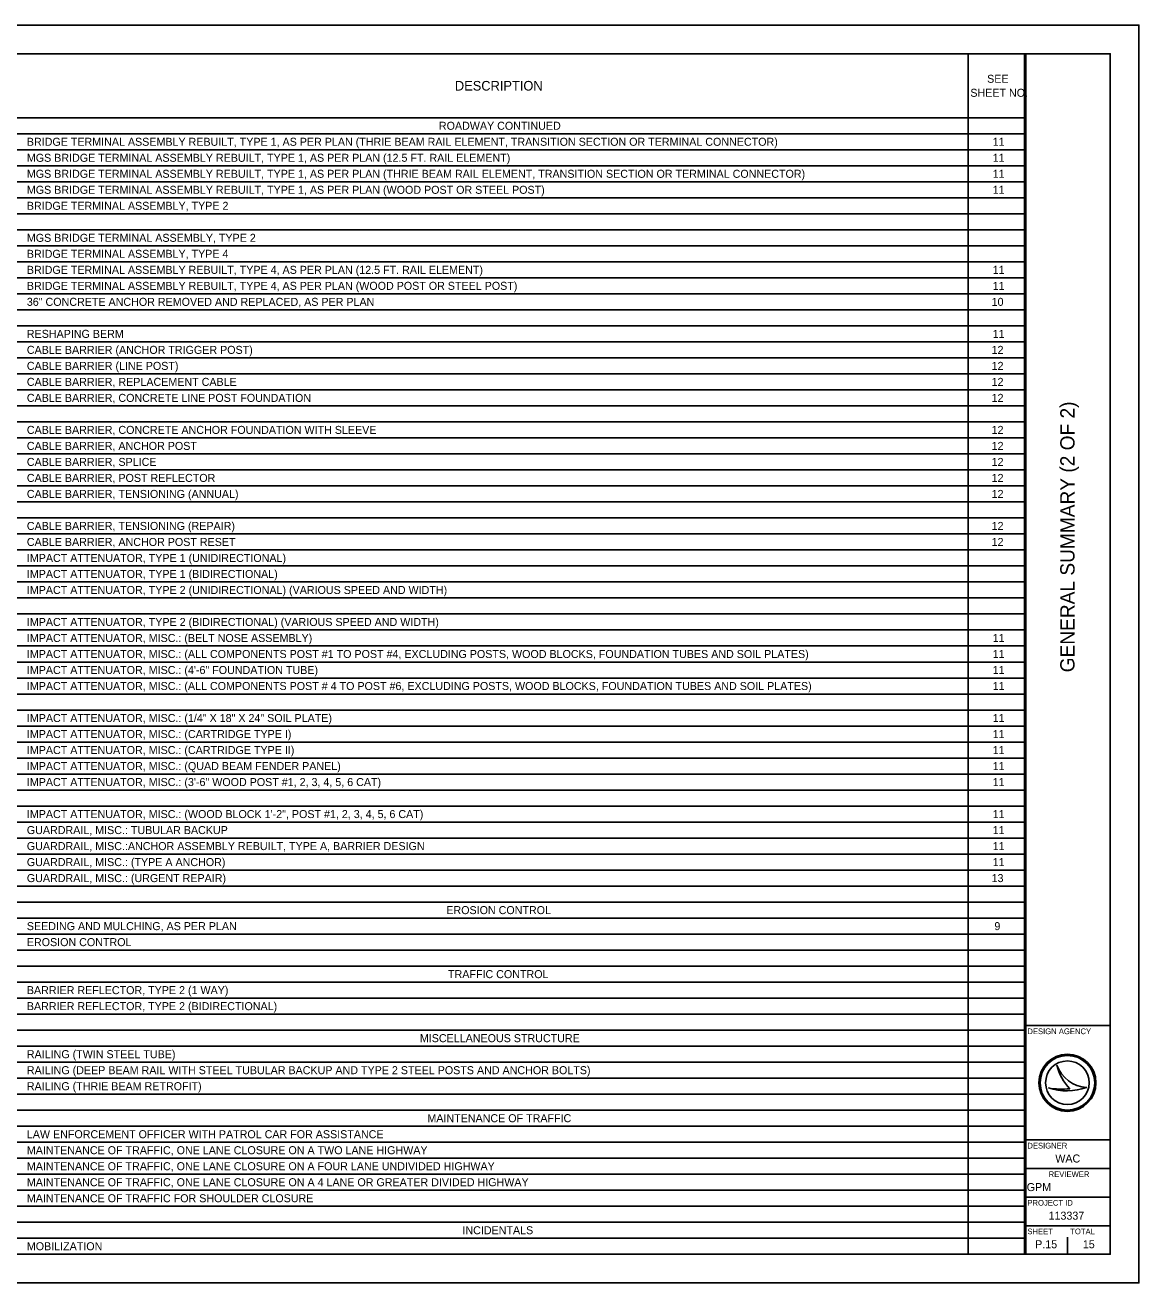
# Model space of a CAD drawing. Extents: x 0 to 34, y 0 to 22.
# Drawn here: x 14.52 to 34, y 0 to 22 of the extents above; entities that cross this region are included whole.
import ezdxf

# ---------------------------------------------------------------- set-up
doc = ezdxf.new("R2010")
doc.units = 0
for name, color, linetype in [('Default', 7, 'Continuous'), ('SH_Border', 7, 'Continuous'), ('SH_Cut_Line', 7, 'Continuous'), ('SH_Data', 7, 'Continuous')]:
    doc.layers.add(name, color=color, linetype=linetype)

msp = doc.modelspace()

# ---------------------------------------------------------------- linework, layer by layer
at = {"layer": 'Default'}
for p, q in [((1.5, 21.5), (32.02, 21.5)), ((31.015, 21.5), (31.015, 0.5)), ((32.02, 21.5), (32.02, 0.5)), ((1.5, 20.38), (32.02, 20.38)), ((1.5, 20.1), (32.02, 20.1)), ((1.5, 19.82), (32.02, 19.82)), ((1.5, 19.54), (32.02, 19.54)), ((1.5, 19.26), (32.02, 19.26)), ((1.5, 18.98), (32.02, 18.98)), ((1.5, 18.7), (32.02, 18.7)), ((1.5, 18.42), (32.02, 18.42)), ((1.5, 18.14), (32.02, 18.14)), ((1.5, 17.86), (32.02, 17.86)), ((1.5, 17.58), (32.02, 17.58)), ((1.5, 17.3), (32.02, 17.3)), ((1.5, 17.02), (32.02, 17.02)), ((1.5, 16.74), (32.02, 16.74)), ((1.5, 16.46), (32.02, 16.46)), ((1.5, 16.18), (32.02, 16.18)), ((1.5, 15.9), (32.02, 15.9)), ((1.5, 15.62), (32.02, 15.62)), ((1.5, 15.34), (32.02, 15.34)), ((1.5, 15.06), (32.02, 15.06)), ((1.5, 14.78), (32.02, 14.78)), ((1.5, 14.5), (32.02, 14.5)), ((1.5, 14.22), (32.02, 14.22)), ((1.5, 13.94), (32.02, 13.94)), ((1.5, 13.66), (32.02, 13.66)), ((1.5, 13.38), (32.02, 13.38)), ((1.5, 13.1), (32.02, 13.1)), ((1.5, 12.82), (32.02, 12.82)), ((1.5, 12.54), (32.02, 12.54)), ((1.5, 12.26), (32.02, 12.26)), ((1.5, 11.98), (32.02, 11.98)), ((1.5, 11.7), (32.02, 11.7)), ((1.5, 11.42), (32.02, 11.42)), ((1.5, 11.14), (32.02, 11.14)), ((1.5, 10.86), (32.02, 10.86)), ((1.5, 10.58), (32.02, 10.58)), ((1.5, 10.3), (32.02, 10.3)), ((1.5, 10.02), (32.02, 10.02)), ((1.5, 9.74), (32.02, 9.74)), ((1.5, 9.46), (32.02, 9.46)), ((1.5, 9.18), (32.02, 9.18)), ((1.5, 8.9), (32.02, 8.9)), ((1.5, 8.62), (32.02, 8.62)), ((1.5, 8.34), (32.02, 8.34)), ((1.5, 8.06), (32.02, 8.06)), ((1.5, 7.78), (32.02, 7.78)), ((1.5, 7.5), (32.02, 7.5)), ((1.5, 7.22), (32.02, 7.22)), ((1.5, 6.94), (32.02, 6.94)), ((1.5, 6.66), (32.02, 6.66)), ((1.5, 6.38), (32.02, 6.38)), ((1.5, 6.1), (32.02, 6.1)), ((1.5, 5.82), (32.02, 5.82)), ((1.5, 5.54), (32.02, 5.54)), ((1.5, 5.26), (32.02, 5.26)), ((1.5, 4.98), (32.02, 4.98)), ((1.5, 4.7), (32.02, 4.7)), ((1.5, 4.42), (32.02, 4.42)), ((1.5, 4.14), (32.02, 4.14)), ((1.5, 3.86), (32.02, 3.86)), ((1.5, 3.58), (32.02, 3.58)), ((1.5, 3.3), (32.02, 3.3)), ((1.5, 3.02), (32.02, 3.02)), ((1.5, 2.74), (32.02, 2.74)), ((1.5, 2.46), (32.02, 2.46)), ((1.5, 2.18), (32.02, 2.18)), ((1.5, 1.9), (32.02, 1.9)), ((1.5, 1.62), (32.02, 1.62)), ((1.5, 1.34), (32.02, 1.34)), ((1.5, 1.06), (32.02, 1.06)), ((1.5, 0.78), (32.02, 0.78)), ((1.5, 0.5), (32.02, 0.5))]:
    msp.add_line(p, q, dxfattribs=at)
at = {"layer": 'SH_Border'}
for p, q in [((32, 0.5), (32, 21.5)), ((32, 4.5), (33.5, 4.5)), ((32, 2.5), (33.5, 2.5)), ((32, 2), (33.5, 2)), ((32, 1.5), (33.5, 1.5)), ((32, 1), (33.5, 1))]:
    msp.add_line(p, q, dxfattribs=at)
msp.add_lwpolyline([(1.5, 21.5), (33.5, 21.5), (33.5, 0.5), (1.5, 0.5)], close=True, dxfattribs=at)
at = {"layer": 'SH_Cut_Line'}
msp.add_lwpolyline([(0, 0), (34, 0), (34, 22), (0, 22)], close=True, dxfattribs=at)
at = {"layer": 'SH_Data'}
for p, q in [((32.567, 3.81), (32.567, 3.81)), ((32.417, 3.41), (32.417, 3.41)), ((32.75, 3.5), (32.75, 3.5)), ((33.087, 3.419), (33.087, 3.419)), ((32.375, 0.675), (32.375, 0.675)), ((32.75, 0.5), (32.75, 0.8))]:
    msp.add_line(p, q, dxfattribs=at)
for radius in [0.5, 0.477, 0.477, 0.382]:
    msp.add_circle((32.75, 3.5), radius, dxfattribs=at)
for centre, radius, start, end in [((33.116, 3.998), 0.58, 198.9257, 198.9319), ((33.347, 3.97), 0.796, 191.6379, 191.6421), ((33.116, 3.998), 0.58, 198.9319, 267.1657), ((33.347, 3.97), 0.796, 191.6421, 226.0947), ((32.739, 4.37), 1.013, 251.4576, 290.0832), ((32.648, 4.654), 1.266, 259.4964, 259.4995), ((32.739, 4.37), 1.013, 251.4527, 251.4576), ((32.648, 4.654), 1.266, 259.4995, 276.6672)]:
    msp.add_arc(centre, radius, start, end, dxfattribs=at)

# ---------------------------------------------------------------- texts
at = {"layer": 'Default'}
for s, height, p in [('SEE ', 0.14, (31.346, 20.992)), ('DESCRIPTION', 0.168, (22.034, 20.856)), ('SHEET NO.', 0.14, (31.052, 20.747)), ('ROADWAY CONTINUED', 0.14, (21.754, 20.17)), ('BRIDGE TERMINAL ASSEMBLY REBUILT, TYPE 1, AS PER PLAN (THRIE BEAM RAIL ELEMENT, TRANSITION SECTION OR TERMINAL CONNECTOR)', 0.14, (14.545, 19.89)), ('11', 0.14, (31.443, 19.89)), ('MGS BRIDGE TERMINAL ASSEMBLY REBUILT, TYPE 1, AS PER PLAN (12.5 FT. RAIL ELEMENT)', 0.14, (14.545, 19.61)), ('11', 0.14, (31.443, 19.61)), ('MGS BRIDGE TERMINAL ASSEMBLY REBUILT, TYPE 1, AS PER PLAN (THRIE BEAM RAIL ELEMENT, TRANSITION SECTION OR TERMINAL CONNECTOR)', 0.14, (14.545, 19.33)), ('11', 0.14, (31.443, 19.33)), ('MGS BRIDGE TERMINAL ASSEMBLY REBUILT, TYPE 1, AS PER PLAN (WOOD POST OR STEEL POST)', 0.14, (14.545, 19.05)), ('11', 0.14, (31.443, 19.05)), ('BRIDGE TERMINAL ASSEMBLY, TYPE 2', 0.14, (14.545, 18.77)), ('MGS BRIDGE TERMINAL ASSEMBLY, TYPE 2', 0.14, (14.545, 18.21)), ('BRIDGE TERMINAL ASSEMBLY, TYPE 4', 0.14, (14.545, 17.93)), ('BRIDGE TERMINAL ASSEMBLY REBUILT, TYPE 4, AS PER PLAN (12.5 FT. RAIL ELEMENT)', 0.14, (14.545, 17.65)), ('11', 0.14, (31.443, 17.65)), ('BRIDGE TERMINAL ASSEMBLY REBUILT, TYPE 4, AS PER PLAN (WOOD POST OR STEEL POST)', 0.14, (14.545, 17.37)), ('11', 0.14, (31.443, 17.37)), ('36" CONCRETE ANCHOR REMOVED AND REPLACED, AS PER PLAN', 0.14, (14.545, 17.09)), ('10', 0.14, (31.424, 17.09)), ('RESHAPING BERM', 0.14, (14.545, 16.53)), ('11', 0.14, (31.443, 16.53)), ('CABLE BARRIER (ANCHOR TRIGGER POST)', 0.14, (14.545, 16.25)), ('12', 0.14, (31.424, 16.25)), ('CABLE BARRIER (LINE POST)', 0.14, (14.545, 15.97)), ('12', 0.14, (31.424, 15.97)), ('CABLE BARRIER, REPLACEMENT CABLE', 0.14, (14.545, 15.69)), ('12', 0.14, (31.424, 15.69)), ('CABLE BARRIER, CONCRETE LINE POST FOUNDATION', 0.14, (14.545, 15.41)), ('12', 0.14, (31.424, 15.41)), ('CABLE BARRIER, CONCRETE ANCHOR FOUNDATION WITH SLEEVE', 0.14, (14.545, 14.85)), ('12', 0.14, (31.424, 14.85)), ('CABLE BARRIER, ANCHOR POST', 0.14, (14.545, 14.57)), ('12', 0.14, (31.424, 14.57)), ('CABLE BARRIER, SPLICE', 0.14, (14.545, 14.29)), ('12', 0.14, (31.424, 14.29)), ('CABLE BARRIER, POST REFLECTOR', 0.14, (14.545, 14.01)), ('12', 0.14, (31.424, 14.01)), ('CABLE BARRIER, TENSIONING (ANNUAL)', 0.14, (14.545, 13.73)), ('12', 0.14, (31.424, 13.73)), ('CABLE BARRIER, TENSIONING (REPAIR)', 0.14, (14.545, 13.17)), ('12', 0.14, (31.424, 13.17)), ('CABLE BARRIER, ANCHOR POST RESET', 0.14, (14.545, 12.89)), ('12', 0.14, (31.424, 12.89)), ('IMPACT ATTENUATOR, TYPE 1 (UNIDIRECTIONAL)', 0.14, (14.545, 12.61)), ('IMPACT ATTENUATOR, TYPE 1 (BIDIRECTIONAL)', 0.14, (14.545, 12.33)), ('IMPACT ATTENUATOR, TYPE 2 (UNIDIRECTIONAL) (VARIOUS SPEED AND WIDTH)', 0.14, (14.545, 12.05)), ('IMPACT ATTENUATOR, TYPE 2 (BIDIRECTIONAL) (VARIOUS SPEED AND WIDTH)', 0.14, (14.545, 11.49)), ('IMPACT ATTENUATOR, MISC.: (BELT NOSE ASSEMBLY)', 0.14, (14.545, 11.21)), ('11', 0.14, (31.443, 11.21)), ('IMPACT ATTENUATOR, MISC.: (ALL COMPONENTS POST #1 TO POST #4, EXCLUDING POSTS, WOOD BLOCKS, FOUNDATION TUBES AND SOIL PLATES)', 0.14, (14.545, 10.93)), ('11', 0.14, (31.443, 10.93)), ('IMPACT ATTENUATOR, MISC.: (4\'-6" FOUNDATION TUBE)', 0.14, (14.545, 10.65)), ('11', 0.14, (31.443, 10.65)), ('IMPACT ATTENUATOR, MISC.: (ALL COMPONENTS POST # 4 TO POST #6, EXCLUDING POSTS, WOOD BLOCKS, FOUNDATION TUBES AND SOIL PLATES)', 0.14, (14.545, 10.37)), ('11', 0.14, (31.443, 10.37)), ('IMPACT ATTENUATOR, MISC.: (1/4" X 18" X 24" SOIL PLATE)', 0.14, (14.545, 9.81)), ('11', 0.14, (31.443, 9.81)), ('IMPACT ATTENUATOR, MISC.: (CARTRIDGE TYPE I)', 0.14, (14.545, 9.53)), ('11', 0.14, (31.443, 9.53)), ('IMPACT ATTENUATOR, MISC.: (CARTRIDGE TYPE II)', 0.14, (14.545, 9.25)), ('11', 0.14, (31.443, 9.25)), ('IMPACT ATTENUATOR, MISC.: (QUAD BEAM FENDER PANEL)', 0.14, (14.545, 8.97)), ('11', 0.14, (31.443, 8.97)), ('IMPACT ATTENUATOR, MISC.: (3\'-6" WOOD POST #1, 2, 3, 4, 5, 6 CAT)', 0.14, (14.545, 8.69)), ('11', 0.14, (31.443, 8.69)), ('IMPACT ATTENUATOR, MISC.: (WOOD BLOCK 1\'-2", POST #1, 2, 3, 4, 5, 6 CAT)', 0.14, (14.545, 8.13)), ('11', 0.14, (31.443, 8.13)), ('GUARDRAIL, MISC.: TUBULAR BACKUP', 0.14, (14.545, 7.85)), ('11', 0.14, (31.443, 7.85)), ('GUARDRAIL, MISC.:ANCHOR ASSEMBLY REBUILT, TYPE A, BARRIER DESIGN', 0.14, (14.545, 7.57)), ('11', 0.14, (31.443, 7.57)), ('GUARDRAIL, MISC.: (TYPE A ANCHOR)', 0.14, (14.545, 7.29)), ('11', 0.14, (31.443, 7.29)), ('GUARDRAIL, MISC.: (URGENT REPAIR)', 0.14, (14.545, 7.01)), ('13', 0.14, (31.424, 7.01)), ('EROSION CONTROL', 0.14, (21.884, 6.45)), ('SEEDING AND MULCHING, AS PER PLAN', 0.14, (14.545, 6.17)), ('9', 0.14, (31.473, 6.17)), ('EROSION CONTROL', 0.14, (14.545, 5.89)), ('TRAFFIC CONTROL', 0.14, (21.914, 5.33)), ('BARRIER REFLECTOR, TYPE 2 (1 WAY)', 0.14, (14.545, 5.05)), ('BARRIER REFLECTOR, TYPE 2 (BIDIRECTIONAL)', 0.14, (14.545, 4.77)), ('MISCELLANEOUS STRUCTURE', 0.14, (21.421, 4.21)), ('RAILING (TWIN STEEL TUBE)', 0.14, (14.545, 3.93)), ('RAILING (DEEP BEAM RAIL WITH STEEL TUBULAR BACKUP AND TYPE 2 STEEL POSTS AND ANCHOR BOLTS)', 0.14, (14.545, 3.65)), ('RAILING (THRIE BEAM RETROFIT)', 0.14, (14.545, 3.37)), ('MAINTENANCE OF TRAFFIC', 0.14, (21.553, 2.81)), ('LAW ENFORCEMENT OFFICER WITH PATROL CAR FOR ASSISTANCE', 0.14, (14.545, 2.53)), ('MAINTENANCE OF TRAFFIC, ONE LANE CLOSURE ON A TWO LANE HIGHWAY', 0.14, (14.545, 2.25)), ('MAINTENANCE OF TRAFFIC, ONE LANE CLOSURE ON A FOUR LANE UNDIVIDED HIGHWAY', 0.14, (14.545, 1.97)), ('MAINTENANCE OF TRAFFIC, ONE LANE CLOSURE ON A 4 LANE OR GREATER DIVIDED HIGHWAY', 0.14, (14.545, 1.69)), ('MAINTENANCE OF TRAFFIC FOR SHOULDER CLOSURE', 0.14, (14.545, 1.41)), ('INCIDENTALS', 0.14, (22.166, 0.85)), ('MOBILIZATION', 0.14, (14.545, 0.57))]:
    msp.add_text(s, height=height, dxfattribs=at).set_placement(p)
at = {"layer": 'SH_Data'}
msp.add_text('GENERAL SUMMARY (2 OF 2)', height=0.25, rotation=90, dxfattribs=at).set_placement((32.875, 10.68))
for s, height, p in [('DESIGN AGENCY', 0.1, (32.05, 4.35)), ('DESIGNER', 0.1, (32.05, 2.35)), ('WAC', 0.14, (32.538, 2.105)), ('REVIEWER', 0.1, (32.422, 1.85)), ('GPM', 0.14, (32.038, 1.605)), ('PROJECT ID', 0.1, (32.05, 1.35)), ('113337', 0.14, (32.42, 1.105)), ('SHEET', 0.1, (32.05, 0.85)), ('TOTAL', 0.1, (32.8, 0.85)), ('P.15', 0.14, (32.185, 0.605)), ('15', 0.14, (33.02, 0.605))]:
    msp.add_text(s, height=height, dxfattribs=at).set_placement(p)

doc.saveas('drawing.dxf')
